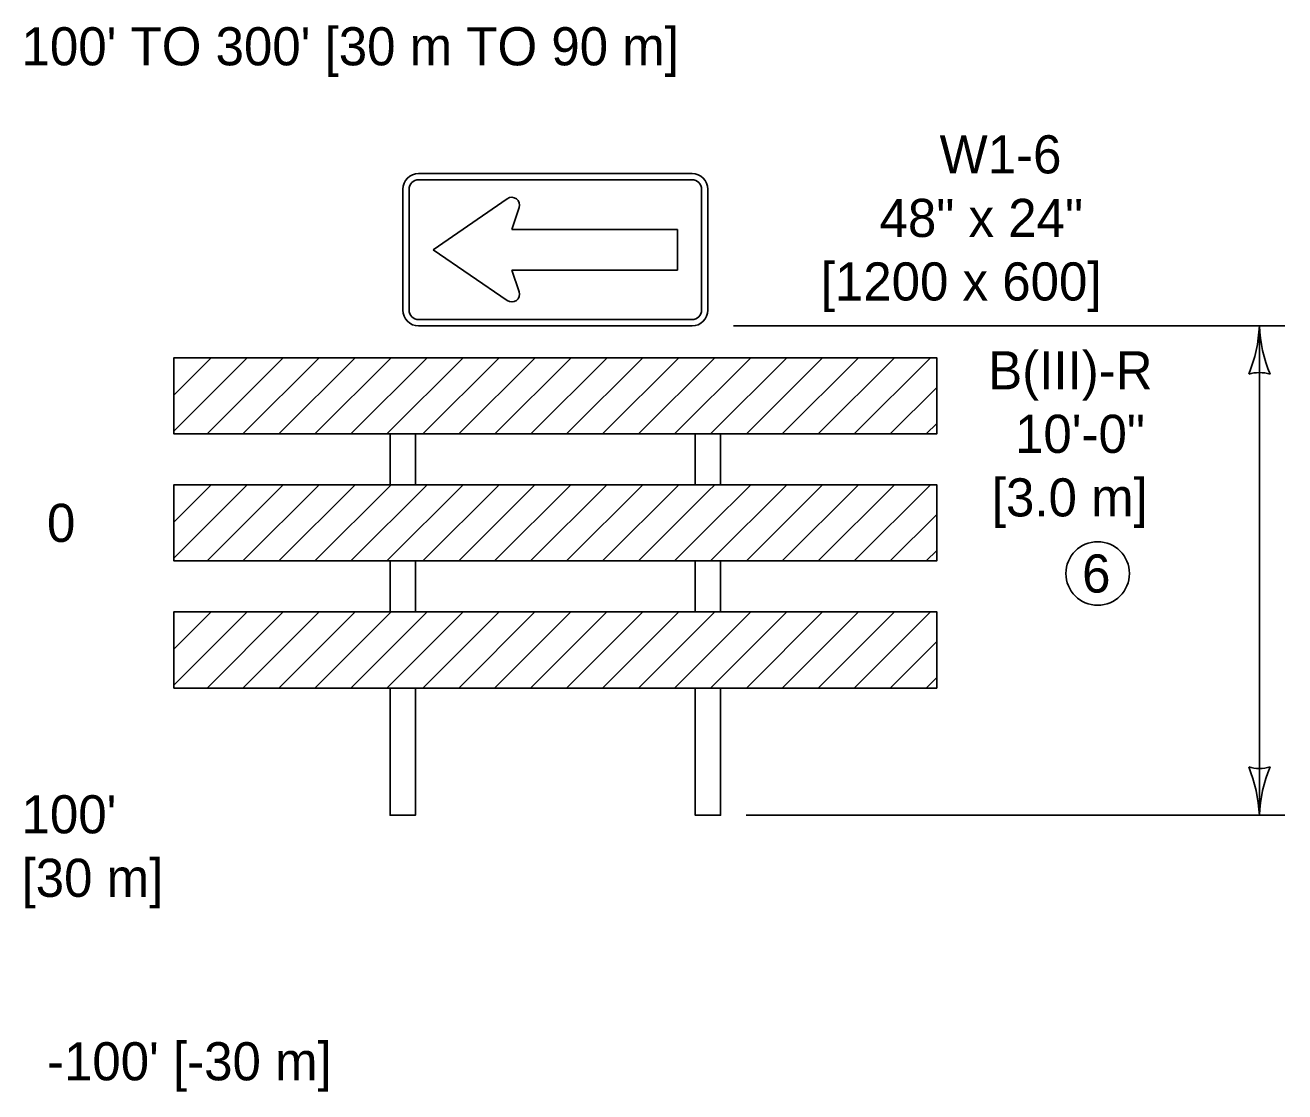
# Model space of a CAD drawing. Extents: x 49991.4 to 50021, y 49987.6 to 50011.4.
# Drawn here: x 50008.971 to 50010.952, y 49989.79 to 49991.469 of the extents above; entities that cross this region are included whole.
import ezdxf

# ---------------------------------------------------------------- set-up
doc = ezdxf.new("R2010")
doc.units = 0
for name, color, linetype in [('Level 1', 7, 'Continuous'), ('Level 2', 7, 'Continuous'), ('Level 3', 7, 'Continuous')]:
    doc.layers.add(name, color=color, linetype=linetype)

msp = doc.modelspace()

# ---------------------------------------------------------------- linework, layer by layer
at = {"layer": 'Level 1'}
for p, q in [((50010.0198, 49991.2354), (50009.5898, 49991.2354)), ((50010.0198, 49991.2254), (50009.5898, 49991.2254)), ((50009.5648, 49991.2104), (50009.5648, 49991.0204)), ((50009.5748, 49991.2104), (50009.5748, 49991.0204)), ((50009.7293, 49991.1956), (50009.6127, 49991.1154)), ((50010.0348, 49991.0204), (50010.0348, 49991.2104)), ((50010.0448, 49991.0204), (50010.0448, 49991.2104)), ((50009.7366, 49991.1474), (50009.7478, 49991.1818)), ((50009.9969, 49991.1474), (50009.7366, 49991.1474)), ((50009.9969, 49991.0834), (50009.9969, 49991.1474)), ((50009.6127, 49991.1154), (50009.7293, 49991.0352)), ((50009.7478, 49991.0491), (50009.7366, 49991.0834)), ((50009.7366, 49991.0834), (50009.7545, 49991.0834)), ((50009.7545, 49991.0834), (50009.9969, 49991.0834)), ((50009.5898, 49991.0054), (50010.0198, 49991.0054)), ((50009.5898, 49990.9954), (50010.0198, 49990.9954)), ((50009.2048, 49990.8299), (50009.3203, 49990.9454)), ((50009.2048, 49990.8865), (50009.2637, 49990.9454)), ((50009.2637, 49990.9454), (50009.2048, 49990.8865)), ((50009.2048, 49990.8299), (50009.3203, 49990.9454)), ((50009.2569, 49990.8254), (50009.3769, 49990.9454)), ((50009.3769, 49990.9454), (50009.2569, 49990.8254)), ((50009.3134, 49990.8254), (50009.4334, 49990.9454)), ((50009.3134, 49990.8254), (50009.4334, 49990.9454)), ((50009.37, 49990.8254), (50009.49, 49990.9454)), ((50009.49, 49990.9454), (50009.37, 49990.8254)), ((50009.4265, 49990.8254), (50009.5465, 49990.9454)), ((50009.4265, 49990.8254), (50009.5465, 49990.9454)), ((50009.4831, 49990.8254), (50009.6031, 49990.9454)), ((50009.5397, 49990.8254), (50009.6597, 49990.9454)), ((50009.5648, 49990.9454), (50009.6198, 49990.9454)), ((50010.0198, 49990.9454), (50009.5898, 49990.9454)), ((50009.5966, 49990.8254), (50009.7166, 49990.9454)), ((50009.6531, 49990.8254), (50009.7731, 49990.9454)), ((50009.7096, 49990.8254), (50009.8296, 49990.9454)), ((50009.7661, 49990.8254), (50009.8861, 49990.9454)), ((50009.8226, 49990.8254), (50009.9426, 49990.9454)), ((50009.8791, 49990.8254), (50009.9991, 49990.9454)), ((50009.9356, 49990.8254), (50010.0556, 49990.9454)), ((50010.0556, 49990.9454), (50009.9856, 49990.9454)), ((50009.9921, 49990.8254), (50010.1121, 49990.9454)), ((50010.0487, 49990.8254), (50010.1687, 49990.9454)), ((50010.1687, 49990.9454), (50010.0487, 49990.8254)), ((50010.1053, 49990.8254), (50010.2253, 49990.9454)), ((50010.1053, 49990.8254), (50010.2253, 49990.9454)), ((50010.1618, 49990.8254), (50010.2818, 49990.9454)), ((50010.2818, 49990.9454), (50010.1618, 49990.8254)), ((50010.2184, 49990.8254), (50010.3384, 49990.9454)), ((50010.2184, 49990.8254), (50010.3384, 49990.9454)), ((50010.275, 49990.8254), (50010.395, 49990.9454)), ((50010.395, 49990.9454), (50010.275, 49990.8254)), ((50010.3315, 49990.8254), (50010.4048, 49990.8987)), ((50010.3315, 49990.8254), (50010.4048, 49990.8987)), ((50010.3881, 49990.8254), (50010.4048, 49990.8421)), ((50010.4048, 49990.8421), (50010.3881, 49990.8254)), ((50009.5848, 49990.7455), (50009.5848, 49990.8254)), ((50010.0248, 49990.7455), (50010.0248, 49990.8254)), ((50009.2048, 49990.63), (50009.3203, 49990.7455)), ((50009.2048, 49990.6865), (50009.2637, 49990.7455)), ((50009.2637, 49990.7455), (50009.2048, 49990.6865)), ((50009.2048, 49990.63), (50009.3203, 49990.7455)), ((50009.2569, 49990.6255), (50009.3769, 49990.7455)), ((50009.3769, 49990.7455), (50009.2569, 49990.6255)), ((50009.3134, 49990.6255), (50009.4334, 49990.7455)), ((50009.3134, 49990.6255), (50009.4334, 49990.7455)), ((50009.37, 49990.6255), (50009.49, 49990.7455)), ((50009.49, 49990.7455), (50009.37, 49990.6255)), ((50009.4265, 49990.6255), (50009.5465, 49990.7455)), ((50009.4265, 49990.6255), (50009.5465, 49990.7455)), ((50009.4831, 49990.6255), (50009.6031, 49990.7455)), ((50009.5397, 49990.6255), (50009.6597, 49990.7455)), ((50009.5962, 49990.6255), (50009.7162, 49990.7455)), ((50009.6528, 49990.6255), (50009.7728, 49990.7455)), ((50009.7093, 49990.6255), (50009.8293, 49990.7455)), ((50009.7659, 49990.6255), (50009.8859, 49990.7455)), ((50009.8225, 49990.6255), (50009.9425, 49990.7455)), ((50009.879, 49990.6255), (50009.999, 49990.7455)), ((50010.0448, 49990.6782), (50010.1121, 49990.7455)), ((50010.0448, 49990.7347), (50010.0556, 49990.7455)), ((50010.0487, 49990.6255), (50010.1687, 49990.7455)), ((50010.1687, 49990.7455), (50010.0487, 49990.6255)), ((50010.1053, 49990.6255), (50010.2253, 49990.7455)), ((50010.1053, 49990.6255), (50010.2253, 49990.7455)), ((50010.1618, 49990.6255), (50010.2818, 49990.7455)), ((50010.2818, 49990.7455), (50010.1618, 49990.6255)), ((50010.2184, 49990.6255), (50010.3384, 49990.7455)), ((50010.2184, 49990.6255), (50010.3384, 49990.7455)), ((50010.275, 49990.6255), (50010.395, 49990.7455)), ((50010.395, 49990.7455), (50010.275, 49990.6255)), ((50009.9356, 49990.6255), (50010.0448, 49990.7347)), ((50010.3315, 49990.6255), (50010.4048, 49990.6987)), ((50010.3315, 49990.6255), (50010.4048, 49990.6987)), ((50009.9921, 49990.6255), (50010.0448, 49990.6782)), ((50010.3881, 49990.6255), (50010.4048, 49990.6422)), ((50010.4048, 49990.6422), (50010.3881, 49990.6255)), ((50009.2048, 49990.43), (50009.3203, 49990.5456)), ((50009.2048, 49990.4866), (50009.2637, 49990.5456)), ((50009.2637, 49990.5456), (50009.2048, 49990.4866)), ((50009.2048, 49990.43), (50009.3203, 49990.5456)), ((50009.2569, 49990.4256), (50009.3769, 49990.5456)), ((50009.3769, 49990.5456), (50009.2569, 49990.4256)), ((50009.3134, 49990.4256), (50009.4334, 49990.5456)), ((50009.3134, 49990.4256), (50009.4334, 49990.5456)), ((50009.37, 49990.4256), (50009.49, 49990.5456)), ((50009.49, 49990.5456), (50009.37, 49990.4256)), ((50009.4265, 49990.4256), (50009.5465, 49990.5456)), ((50009.4265, 49990.4256), (50009.5465, 49990.5456)), ((50009.4831, 49990.4256), (50009.6031, 49990.5456)), ((50009.6031, 49990.5456), (50009.4831, 49990.4256)), ((50009.5397, 49990.4256), (50009.6597, 49990.5456)), ((50009.5397, 49990.4256), (50009.6597, 49990.5456)), ((50009.5962, 49990.4256), (50009.7162, 49990.5456)), ((50009.7162, 49990.5456), (50009.5962, 49990.4256)), ((50009.6528, 49990.4256), (50009.7728, 49990.5456)), ((50009.6528, 49990.4256), (50009.7728, 49990.5456)), ((50009.7093, 49990.4256), (50009.8293, 49990.5456)), ((50009.8293, 49990.5456), (50009.7093, 49990.4256)), ((50009.7659, 49990.4256), (50009.8859, 49990.5456)), ((50009.7659, 49990.4256), (50009.8859, 49990.5456)), ((50009.8225, 49990.4256), (50009.9425, 49990.5456)), ((50009.9425, 49990.5456), (50009.8225, 49990.4256)), ((50009.879, 49990.4256), (50009.999, 49990.5456)), ((50009.879, 49990.4256), (50009.999, 49990.5456)), ((50009.9356, 49990.4256), (50010.0556, 49990.5456)), ((50010.0556, 49990.5456), (50009.9356, 49990.4256)), ((50009.9921, 49990.4256), (50010.1121, 49990.5456)), ((50009.9921, 49990.4256), (50010.1121, 49990.5456)), ((50010.0487, 49990.4256), (50010.1687, 49990.5456)), ((50010.1687, 49990.5456), (50010.0487, 49990.4256)), ((50010.1053, 49990.4256), (50010.2253, 49990.5456)), ((50010.1053, 49990.4256), (50010.2253, 49990.5456)), ((50010.1618, 49990.4256), (50010.2818, 49990.5456)), ((50010.2818, 49990.5456), (50010.1618, 49990.4256)), ((50010.2184, 49990.4256), (50010.3384, 49990.5456)), ((50010.2184, 49990.4256), (50010.3384, 49990.5456)), ((50010.275, 49990.4256), (50010.395, 49990.5456)), ((50010.395, 49990.5456), (50010.275, 49990.4256)), ((50010.3315, 49990.4256), (50010.4048, 49990.4988)), ((50010.3315, 49990.4256), (50010.4048, 49990.4988)), ((50010.3881, 49990.4256), (50010.4048, 49990.4423)), ((50010.4048, 49990.4423), (50010.3881, 49990.4256))]:
    msp.add_line(p, q, dxfattribs=at)
for points in [[(50010.0448, 49990.8254), (50009.2048, 49990.8254), (50009.2048, 49990.9454), (50009.5648, 49990.9454)], [(50009.3203, 49990.9454), (50009.2637, 49990.9454)], [(50009.4334, 49990.9454), (50009.3769, 49990.9454)], [(50009.6597, 49990.9454), (50009.6198, 49990.9454), (50009.6031, 49990.9454), (50009.4831, 49990.8254), (50009.5397, 49990.8254), (50009.6597, 49990.9454)], [(50009.5465, 49990.9454), (50009.49, 49990.9454)], [(50009.7731, 49990.9454), (50009.7166, 49990.9454), (50009.5966, 49990.8254), (50009.6531, 49990.8254), (50009.7731, 49990.9454)], [(50009.8861, 49990.9454), (50009.8296, 49990.9454), (50009.7096, 49990.8254), (50009.7661, 49990.8254), (50009.8861, 49990.9454)], [(50009.9991, 49990.9454), (50009.9856, 49990.9454), (50009.9426, 49990.9454), (50009.8226, 49990.8254), (50009.8791, 49990.8254), (50009.9991, 49990.9454)], [(50009.9356, 49990.8254), (50009.9921, 49990.8254), (50010.1121, 49990.9454), (50010.0556, 49990.9454), (50009.9356, 49990.8254)], [(50010.0448, 49990.9454), (50010.4048, 49990.9454), (50010.4048, 49990.8254), (50010.0448, 49990.8254)], [(50010.2253, 49990.9454), (50010.1687, 49990.9454)], [(50010.3384, 49990.9454), (50010.2818, 49990.9454)], [(50010.4048, 49990.8987), (50010.4048, 49990.9454), (50010.395, 49990.9454)], [(50009.2048, 49990.8865), (50009.2048, 49990.8299)], [(50010.3881, 49990.8254), (50010.4048, 49990.8254), (50010.4048, 49990.8421)], [(50009.2569, 49990.8254), (50009.3134, 49990.8254)], [(50009.37, 49990.8254), (50009.4265, 49990.8254)], [(50009.5448, 49990.7454), (50009.5448, 49990.8254)], [(50010.0487, 49990.8254), (50010.1053, 49990.8254)], [(50010.0648, 49990.8254), (50010.0648, 49990.7455)], [(50010.1618, 49990.8254), (50010.2184, 49990.8254)], [(50010.275, 49990.8254), (50010.3315, 49990.8254)], [(50010.0448, 49990.7455), (50010.4048, 49990.7455), (50010.4048, 49990.6255), (50009.2048, 49990.6255), (50009.2048, 49990.7455), (50010.0448, 49990.7455)], [(50009.3203, 49990.7455), (50009.2637, 49990.7455)], [(50009.4334, 49990.7455), (50009.3769, 49990.7455)], [(50009.6597, 49990.7455), (50009.6031, 49990.7455), (50009.4831, 49990.6255), (50009.5397, 49990.6255), (50009.6597, 49990.7455)], [(50009.5465, 49990.7455), (50009.49, 49990.7455)], [(50009.7728, 49990.7455), (50009.7162, 49990.7455), (50009.5962, 49990.6255), (50009.6528, 49990.6255), (50009.7728, 49990.7455)], [(50009.8859, 49990.7455), (50009.8293, 49990.7455), (50009.7093, 49990.6255), (50009.7659, 49990.6255), (50009.8859, 49990.7455)], [(50009.999, 49990.7455), (50009.9425, 49990.7455), (50009.8225, 49990.6255), (50009.879, 49990.6255), (50009.999, 49990.7455)], [(50009.9356, 49990.6255), (50009.9921, 49990.6255), (50010.0448, 49990.6782), (50010.1121, 49990.7455), (50010.0648, 49990.7455), (50010.0556, 49990.7455), (50010.0448, 49990.7347), (50009.9356, 49990.6255)], [(50010.2253, 49990.7455), (50010.1687, 49990.7455)], [(50010.3384, 49990.7455), (50010.2818, 49990.7455)], [(50010.4048, 49990.6987), (50010.4048, 49990.7455), (50010.395, 49990.7455)], [(50009.2048, 49990.6865), (50009.2048, 49990.63)], [(50010.3881, 49990.6255), (50010.4048, 49990.6255), (50010.4048, 49990.6422)], [(50009.2569, 49990.6255), (50009.3134, 49990.6255)], [(50009.37, 49990.6255), (50009.4265, 49990.6255)], [(50009.5448, 49990.5456), (50009.5448, 49990.6255)], [(50009.5848, 49990.6255), (50009.5848, 49990.5456)], [(50010.0248, 49990.5456), (50010.0248, 49990.6255)], [(50010.0487, 49990.6255), (50010.1053, 49990.6255)], [(50010.0648, 49990.6255), (50010.0648, 49990.5456)], [(50010.1618, 49990.6255), (50010.2184, 49990.6255)], [(50010.275, 49990.6255), (50010.3315, 49990.6255)], [(50010.1121, 49990.5456), (50010.4048, 49990.5456), (50010.4048, 49990.4256), (50009.2048, 49990.4256), (50009.2048, 49990.5456), (50009.49, 49990.5456)], [(50009.3203, 49990.5456), (50009.2637, 49990.5456)], [(50009.4334, 49990.5456), (50009.3769, 49990.5456)], [(50009.5465, 49990.5456), (50009.49, 49990.5456)], [(50009.5465, 49990.5456), (50010.0556, 49990.5456)], [(50009.6597, 49990.5456), (50009.6031, 49990.5456)], [(50009.7728, 49990.5456), (50009.7162, 49990.5456)], [(50009.8859, 49990.5456), (50009.8293, 49990.5456)], [(50009.999, 49990.5456), (50009.9425, 49990.5456)], [(50010.1121, 49990.5456), (50010.0556, 49990.5456)], [(50010.2253, 49990.5456), (50010.1687, 49990.5456)], [(50010.3384, 49990.5456), (50010.2818, 49990.5456)], [(50010.4048, 49990.4988), (50010.4048, 49990.5456), (50010.395, 49990.5456)], [(50009.2048, 49990.4866), (50009.2048, 49990.43)], [(50010.3881, 49990.4256), (50010.4048, 49990.4256), (50010.4048, 49990.4423)], [(50009.2569, 49990.4256), (50009.3134, 49990.4256)], [(50009.37, 49990.4256), (50009.4265, 49990.4256)], [(50009.4831, 49990.4256), (50009.5397, 49990.4256)], [(50009.5848, 49990.4254), (50009.5848, 49990.2254), (50009.5448, 49990.2254), (50009.5448, 49990.4254)], [(50009.5962, 49990.4256), (50009.6528, 49990.4256)], [(50009.7093, 49990.4256), (50009.7659, 49990.4256)], [(50009.8225, 49990.4256), (50009.879, 49990.4256)], [(50009.9356, 49990.4256), (50009.9921, 49990.4256)], [(50010.0648, 49990.4254), (50010.0648, 49990.2254), (50010.0248, 49990.2254), (50010.0248, 49990.4254)], [(50010.0487, 49990.4256), (50010.1053, 49990.4256)], [(50010.1618, 49990.4256), (50010.2184, 49990.4256)], [(50010.275, 49990.4256), (50010.3315, 49990.4256)]]:
    msp.add_lwpolyline(points, dxfattribs=at)
for centre, radius, start, end in [((50009.5898, 49991.2104), 0.025, 90, 180), ((50010.0198, 49991.2104), 0.025, 0, 90), ((50009.5898, 49991.2104), 0.015, 90, 180), ((50010.0198, 49991.2104), 0.015, 0, 90), ((50009.7362, 49991.1856), 0.0122, 342.0418, 124.5194), ((50009.7362, 49991.0453), 0.0122, 235.4806, 17.9582), ((50009.5898, 49991.0204), 0.025, 180, 270), ((50009.5898, 49991.0204), 0.015, 180, 270), ((50010.0198, 49991.0204), 0.025, 270, 0), ((50010.0198, 49991.0204), 0.015, 270, 0)]:
    msp.add_arc(centre, radius, start, end, dxfattribs=at)
at = {"layer": 'Level 2'}
msp.add_circle((50010.6579, 49990.6058), 0.05, dxfattribs=at)
at = {"layer": 'Level 3'}
for p, q in [((50010.0848, 49990.9954), (50010.9522, 49990.9954)), ((50010.9122, 49990.2254), (50010.9122, 49990.9954)), ((50010.1048, 49990.2254), (50010.9522, 49990.2254))]:
    msp.add_line(p, q, dxfattribs=at)
for centre, radius, start, end in [((50010.6901, 49991.0046), 0.2223, 337.456, 357.6395), ((50011.1449, 49991.0069), 0.233, 182.8273, 202.0772), ((50010.9122, 49990.8672), 0.0548, 72.1388, 107.8612), ((50010.9122, 49990.3536), 0.0548, 252.1388, 287.8612), ((50010.6795, 49990.2139), 0.233, 2.8273, 22.0772), ((50011.1344, 49990.2162), 0.2223, 157.456, 177.6395)]:
    msp.add_arc(centre, radius, start, end, dxfattribs=at)

# ---------------------------------------------------------------- texts
at = {"layer": 'Level 2'}
for s, p in [("100' TO 300' [30 m TO 90 m]", (50008.9652, 49991.4055)), ('W1-6', (50010.4092, 49991.2354)), ('48" x 24"', (50010.3148, 49991.1354)), ('[1200 x 600]', (50010.2223, 49991.0354)), ('B(III)-R', (50010.4857, 49990.8956)), (' 10\'-0"', (50010.5056, 49990.7956)), ('[3.0 m]', (50010.4914, 49990.6956)), ('0', (50009.0052, 49990.6555)), ('6', (50010.6334, 49990.5758)), ("100'", (50008.9652, 49990.1969)), ('[30 m]', (50008.9652, 49990.0969)), ("-100' [-30 m]", (50009.0052, 49989.8082))]:
    msp.add_text(s, height=0.06, dxfattribs=at).set_placement(p)

doc.saveas('drawing.dxf')
